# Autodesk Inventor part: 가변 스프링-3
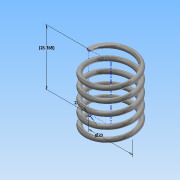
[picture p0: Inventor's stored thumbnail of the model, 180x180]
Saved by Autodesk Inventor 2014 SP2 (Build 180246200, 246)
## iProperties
Created: 2016-01
Part Number: 가변 스프링-3
Material: 스테인레스 스틸
Document SubType Name: Modeling
Designer: Administrator
Density: 8.08 g/cm^3
Appearance: 반연마
Mass: 7.841 g
Surface Area: 19.6955 cm^2
Volume: 0.97042 cm^3
Author: Administrator
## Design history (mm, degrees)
sketch "스케치2"
  geometry: L1 (0, 0)-(10, 0); L2 (10, 0)-(10, 25.358); L3 (10, 25.358)-(0, 25.358); L4 (0, 25.358)-(0, 0); C1 r 1 at (10, 0)
  constraints: 8 end point, 2 parallel, 1 centre point, 1 coincident, 1 horizontal, 1 perpendicular
  dimensions: "d0" = 2 diameter of C1; "d1" = 20 diameter of L2 L4; "d2" = 25.35829 distance between parallel lines of L3 L1 (derived)
feature "코일1" pitch "d3" = 10; turns "d5" = 5; dims "d4" = 25.35829 (= d2), "d6" = 0, angle "d7" = 90 deg, angle "d8" = 90 deg, "d9" = 0, "d10" = 0
sketch "스케치3"
  geometry: L1 (-11, 0)-(-9, 0) reference; 1 further point
  constraints: 1 horizontal alignment
extrude "돌출1" cut sketch "스케치3" stored distance "d11" = 10; taper "d12" = 0 deg
node "작업 평면1"
sketch "스케치4"
  geometry: L1 (1, 0)-(-1, 0) reference; 1 further point
  constraints: 1 horizontal alignment
extrude "돌출2" cut sketch "스케치4" stored distance "d14" = 10; taper "d15" = 0 deg
node "솔리드1"
node "절단 모서리 투영1"
node "절단 모서리 투영2"
other parameters: "d13" = 0
